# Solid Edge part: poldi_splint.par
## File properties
Author: Mac
Template: Normal.par
Last saved by: Mac
Revision: 4
Application: Solid Edge
Material: Stainless steel
Face Style: Steel
Fill Style: ANSI32(Steel)
Virtual Style: Stainless steel
Coef. of Thermal Exp: 1.6e-05
Thermal Conductivity: 17.0
Specific Heat: 502.0
Modulus of Elasticity: 193053196000.0
Poission's Ratio: 0.29
Yield Stress: 310264065.0
Ultimate Stress: 641212401.0
Elongation: 0.0
Density: 7750,000 kg/m^3
Accuracy: 0,990
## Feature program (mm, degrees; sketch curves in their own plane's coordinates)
swept protrusion "unnamed SweptProtrusion 1"
swept protrusion "unnamed SweptProtrusion 2"
body pattern "unnamed BodyPattern 1"
pattern "unnamed Pattern 1"
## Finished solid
Body 1: solid body, 42 faces, 84 edges, 44 vertices.
  Faces by surface: torus 18, cylinder 12, spline 8, plane 4
  Edges by curve: circle 57, line 19, spline 8
Bounding box of the edges (mm; curved faces can reach further): 0.741 x 1.229 x 0.098, from (-0.469, -0.8069, -0.0487) to (0.2715, 0.4223, 0.0487).
Cylindrical faces by radius (mm): R0.01 x4, R0.05 x2, R0.0888 x2, R0.0896 x2, R0.5568 x2
Toroidal faces (ring radius, tube radius in mm): R0.0788 r0.01 x4, R0.0796 r0.01 x4, R0.0888 r0.05 x2, R0.0896 r0.05 x2, R0.5468 r0.01 x4, R0.5568 r0.05 x2
Planar faces by outward normal: +x 1, oblique 3
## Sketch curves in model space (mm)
arc centre (-0.4591, 0.0143, 0.0387) radius 0.01 from (-0.4566, 0.014, 0.0484) through (-0.4654, 0.015, 0.0465) to (-0.469, 0.0154, 0.0387)
arc centre (-0.469, 0.0154, 0) radius 0.05 from (-0.4566, 0.014, 0.0484) through (-0.4193, 0.0099, -0.0015) to (-0.4566, 0.014, -0.0484)
arc centre (-0.4591, 0.0143, -0.0387) radius 0.01 from (-0.469, 0.0154, -0.0387) through (-0.4649, 0.0149, -0.0468) to (-0.4566, 0.014, -0.0484)
line (-0.469, 0.0154, -0.0387) -> (-0.469, 0.0154, 0.0387)
arc centre (0.0844, -0.0456, 0) radius 0.5568 from (-0.469, 0.0154, 0) through (-0.3969, 0.2343, 0) to (-0.2422, 0.4052, 0)
arc centre (-0.1896, 0.3326, 0) radius 0.0896 from (-0.1, 0.3326, 0) through (-0.1513, 0.4137, 0) to (-0.2422, 0.4052, 0)
arc centre (-0.1, -0.7669, 0.0387) radius 0.01 from (-0.1, -0.7569, 0.0387) through (-0.1, -0.761, 0.0468) to (-0.1, -0.7694, 0.0484)
arc centre (-0.1, -0.7569, 0) radius 0.05 from (-0.1, -0.7694, -0.0484) through (-0.1001, -0.8069, 0.0015) to (-0.1, -0.7694, 0.0484)
arc centre (-0.1, -0.7669, -0.0387) radius 0.01 from (-0.1, -0.7694, -0.0484) through (-0.1, -0.7605, -0.0465) to (-0.1, -0.7569, -0.0387)
line (-0.1, -0.7569, -0.0387) -> (-0.1, -0.7569, 0.0387)
spline (-0.1244, -0.3649, 0) -> (-0.2225, -0.613, 0) -> (-0.1, -0.7569, 0)
arc centre (-0.1888, -0.3038, 0) radius 0.0888 from (-0.1, -0.3038, 0) through (-0.1063, -0.3367, 0) to (-0.1244, -0.3649, 0)
line (-0.1, 0.3326, 0) -> (-0.1, -0.3038, 0)
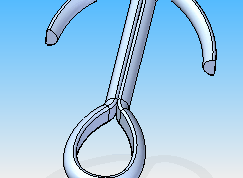
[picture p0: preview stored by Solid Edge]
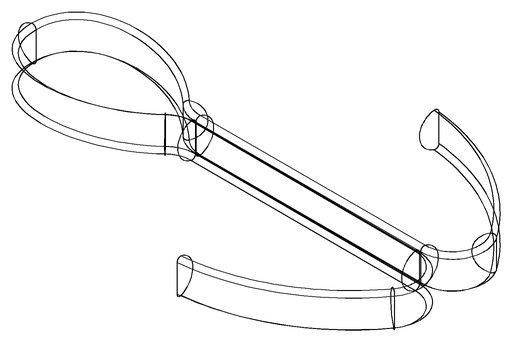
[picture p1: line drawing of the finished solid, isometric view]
